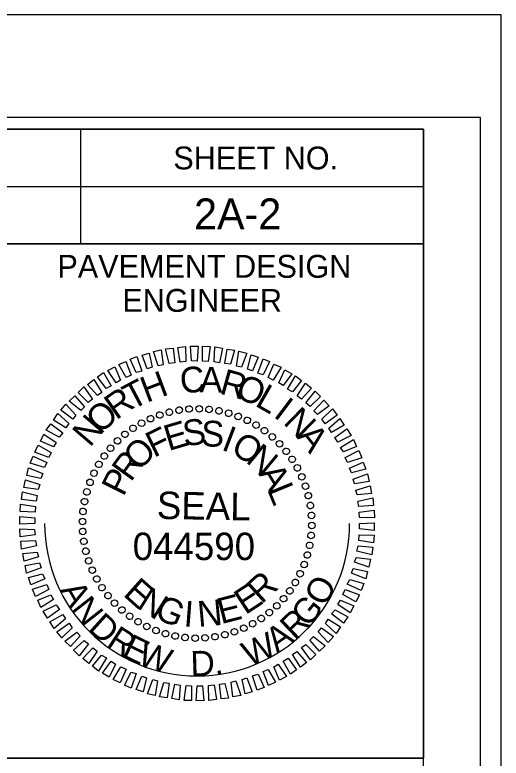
# Model space of a CAD drawing. Extents: x 1497225 to 1499181, y 579958 to 582278.
# Drawn here: x 1498802.9 to 1498909.2, y 580895.5 to 581058 of the extents above; entities that cross this region are included whole.
import ezdxf

# ---------------------------------------------------------------- set-up
doc = ezdxf.new("R2010")
doc.units = 0
for name, color, linetype in [('Scratch_Level_0', 7, 'Continuous'), ('Sheet Cutting Line CELL', 7, 'Continuous'), ('Sheet Data Field CELL', 7, 'Continuous'), ('Sheet Plot Border Inside CELL', 7, 'Continuous'), ('Sheet Plot Border Outside CELL', 7, 'Continuous'), ('Sheet Professional Seal CELL', 7, 'Continuous'), ('Sheet Sticker Exception Certification CELL', 7, 'Continuous'), ('Sheet Typical CELL', 7, 'Continuous')]:
    doc.layers.add(name, color=color, linetype=linetype)

msp = doc.modelspace()

# ---------------------------------------------------------------- linework, layer by layer
at = {"layer": 'Scratch_Level_0'}
msp.add_arc((1498842.73, 580946.79), 33.36, 180, 360, dxfattribs=at)
at = {"layer": 'Sheet Cutting Line CELL'}
msp.add_line((1498909.23, 581058.02), (1497225.23, 581058.02), dxfattribs=at)
at = {"layer": 'Sheet Plot Border Inside CELL'}
msp.add_lwpolyline([(1498904.73, 581035.57), (1497238.23, 581035.57), (1497238.23, 579980.47), (1498904.73, 579980.47)], close=True, dxfattribs=at)
at = {"layer": 'Sheet Plot Border Outside CELL'}
msp.add_lwpolyline([(1498909.23, 581058.02), (1497225.23, 581058.02), (1497225.23, 579958.02), (1498909.23, 579958.02)], close=True, dxfattribs=at)
at = {"layer": 'Sheet Professional Seal CELL'}
for p, q in [((1498838.83, 580971.54), (1498838.83, 580971.54)), ((1498840.98, 580971.84), (1498840.98, 580971.84)), ((1498843.18, 580971.89), (1498843.18, 580971.89)), ((1498845.38, 580971.74), (1498845.38, 580971.74)), ((1498847.53, 580971.39), (1498847.53, 580971.39)), ((1498832.53, 580969.74), (1498832.53, 580969.74)), ((1498834.53, 580970.54), (1498834.53, 580970.54)), ((1498836.63, 580971.14), (1498836.63, 580971.14)), ((1498849.63, 580970.94), (1498849.63, 580970.94)), ((1498851.73, 580970.24), (1498851.73, 580970.24)), ((1498830.58, 580968.74), (1498830.58, 580968.74)), ((1498853.73, 580969.34), (1498853.73, 580969.34)), ((1498855.68, 580968.34), (1498855.68, 580968.34)), ((1498826.93, 580966.34), (1498826.93, 580966.34)), ((1498828.68, 580967.59), (1498828.68, 580967.59)), ((1498857.48, 580967.09), (1498857.48, 580967.09)), ((1498825.28, 580964.84), (1498825.28, 580964.84)), ((1498859.23, 580965.74), (1498859.23, 580965.74)), ((1498823.78, 580963.29), (1498823.78, 580963.29)), ((1498860.78, 580964.24), (1498860.78, 580964.24)), ((1498822.43, 580961.54), (1498822.43, 580961.54)), ((1498862.28, 580962.59), (1498862.28, 580962.59)), ((1498863.53, 580960.84), (1498863.53, 580960.84)), ((1498821.18, 580959.74), (1498821.18, 580959.74)), ((1498864.68, 580958.94), (1498864.68, 580958.94)), ((1498820.18, 580957.79), (1498820.18, 580957.79)), ((1498865.68, 580956.99), (1498865.68, 580956.99)), ((1498819.28, 580955.79), (1498819.28, 580955.79)), ((1498866.48, 580954.99), (1498866.48, 580954.99)), ((1498818.58, 580953.69), (1498818.58, 580953.69)), ((1498867.08, 580952.89), (1498867.08, 580952.89)), ((1498818.13, 580951.59), (1498818.13, 580951.59)), ((1498867.48, 580950.69), (1498867.48, 580950.69)), ((1498817.78, 580949.44), (1498817.78, 580949.44)), ((1498867.78, 580948.54), (1498867.78, 580948.54)), ((1498817.63, 580947.24), (1498817.63, 580947.24)), ((1498842.73, 580946.79), (1498842.73, 580946.79)), ((1498867.83, 580946.34), (1498867.83, 580946.34)), ((1498817.68, 580945.04), (1498817.68, 580945.04)), ((1498867.68, 580944.14), (1498867.68, 580944.14)), ((1498817.98, 580942.89), (1498817.98, 580942.89)), ((1498867.33, 580941.99), (1498867.33, 580941.99)), ((1498818.38, 580940.69), (1498818.38, 580940.69)), ((1498866.88, 580939.89), (1498866.88, 580939.89)), ((1498818.98, 580938.59), (1498818.98, 580938.59)), ((1498866.18, 580937.79), (1498866.18, 580937.79)), ((1498819.78, 580936.59), (1498819.78, 580936.59)), ((1498865.28, 580935.79), (1498865.28, 580935.79)), ((1498820.78, 580934.64), (1498820.78, 580934.64)), ((1498864.28, 580933.84), (1498864.28, 580933.84)), ((1498821.93, 580932.74), (1498821.93, 580932.74)), ((1498823.18, 580930.99), (1498823.18, 580930.99)), ((1498863.03, 580932.04), (1498863.03, 580932.04)), ((1498824.68, 580929.34), (1498824.68, 580929.34)), ((1498861.68, 580930.29), (1498861.68, 580930.29)), ((1498826.23, 580927.84), (1498826.23, 580927.84)), ((1498860.18, 580928.74), (1498860.18, 580928.74)), ((1498827.98, 580926.49), (1498827.98, 580926.49)), ((1498856.78, 580925.99), (1498856.78, 580925.99)), ((1498858.53, 580927.24), (1498858.53, 580927.24)), ((1498829.78, 580925.24), (1498829.78, 580925.24)), ((1498831.73, 580924.24), (1498831.73, 580924.24)), ((1498854.88, 580924.84), (1498854.88, 580924.84)), ((1498833.73, 580923.34), (1498833.73, 580923.34)), ((1498835.83, 580922.64), (1498835.83, 580922.64)), ((1498848.83, 580922.44), (1498848.83, 580922.44)), ((1498850.93, 580923.04), (1498850.93, 580923.04)), ((1498852.93, 580923.84), (1498852.93, 580923.84)), ((1498837.93, 580922.19), (1498837.93, 580922.19)), ((1498840.08, 580921.84), (1498840.08, 580921.84)), ((1498842.28, 580921.69), (1498842.28, 580921.69)), ((1498844.48, 580921.74), (1498844.48, 580921.74)), ((1498846.63, 580922.04), (1498846.63, 580922.04))]:
    msp.add_line(p, q, dxfattribs=at)
for points in [[(1498834.23, 580981.24), (1498833.18, 580984.39), (1498834.88, 580984.74), (1498835.28, 580981.49)], [(1498836.63, 580981.79), (1498835.83, 580984.99), (1498837.48, 580985.14), (1498837.83, 580981.94)], [(1498839.03, 580982.09), (1498838.48, 580985.29), (1498840.18, 580985.49), (1498840.23, 580982.24)], [(1498841.53, 580982.34), (1498841.28, 580985.59), (1498842.93, 580985.54), (1498842.73, 580982.29)], [(1498843.93, 580982.29), (1498843.93, 580985.54), (1498845.58, 580985.49), (1498845.13, 580982.24)], [(1498846.43, 580982.14), (1498846.63, 580985.39), (1498848.28, 580985.09), (1498847.63, 580981.94)], [(1498848.83, 580981.74), (1498849.28, 580984.94), (1498850.93, 580984.69), (1498850.03, 580981.59)], [(1498851.38, 580981.19), (1498851.88, 580984.44), (1498853.58, 580984.04), (1498852.43, 580980.94)], [(1498829.38, 580979.79), (1498828.08, 580982.69), (1498829.58, 580983.29), (1498830.63, 580980.09)], [(1498831.83, 580980.59), (1498830.68, 580983.59), (1498832.23, 580984.04), (1498832.88, 580980.94)], [(1498853.78, 580980.54), (1498854.53, 580983.64), (1498856.08, 580983.14), (1498854.83, 580980.19)], [(1498856.03, 580979.64), (1498857.18, 580982.79), (1498858.58, 580982.19), (1498857.18, 580979.29)], [(1498825.03, 580977.54), (1498823.18, 580980.24), (1498824.73, 580981.04), (1498825.98, 580978.14)], [(1498827.18, 580978.74), (1498825.58, 580981.54), (1498827.13, 580982.24), (1498828.28, 580979.19)], [(1498858.28, 580978.69), (1498859.53, 580981.64), (1498861.08, 580980.94), (1498859.38, 580978.14)], [(1498822.83, 580976.29), (1498820.98, 580978.84), (1498822.28, 580979.79), (1498823.93, 580976.89)], [(1498860.58, 580977.54), (1498861.93, 580980.39), (1498863.43, 580979.54), (1498861.53, 580976.94)], [(1498820.93, 580974.79), (1498818.78, 580977.19), (1498820.13, 580978.24), (1498821.88, 580975.44)], [(1498862.53, 580976.19), (1498864.28, 580979.09), (1498865.58, 580978.04), (1498863.63, 580975.59)], [(1498818.93, 580973.24), (1498816.73, 580975.44), (1498817.93, 580976.64), (1498819.88, 580973.94)], [(1498864.58, 580974.69), (1498866.43, 580977.44), (1498867.73, 580976.34), (1498865.53, 580973.99)], [(1498817.28, 580971.49), (1498814.73, 580973.54), (1498815.98, 580974.69), (1498818.08, 580972.29)], [(1498866.48, 580973.14), (1498868.53, 580975.74), (1498869.73, 580974.54), (1498867.43, 580972.39)], [(1498815.53, 580969.59), (1498812.93, 580971.54), (1498814.03, 580972.84), (1498816.23, 580970.49)], [(1498868.28, 580971.39), (1498870.43, 580973.74), (1498871.63, 580972.54), (1498869.03, 580970.59)], [(1498870.03, 580969.59), (1498872.33, 580971.84), (1498873.38, 580970.49), (1498870.73, 580968.59)], [(1498814.03, 580967.69), (1498811.33, 580969.39), (1498812.28, 580970.84), (1498814.68, 580968.64)], [(1498871.53, 580967.64), (1498873.98, 580969.74), (1498874.93, 580968.29), (1498872.13, 580966.69)], [(1498812.53, 580965.69), (1498809.73, 580967.19), (1498810.73, 580968.59), (1498813.33, 580966.59)], [(1498811.33, 580963.54), (1498808.48, 580964.79), (1498809.23, 580966.34), (1498811.93, 580964.49)], [(1498872.83, 580965.59), (1498875.48, 580967.49), (1498876.43, 580965.99), (1498873.53, 580964.59)], [(1498874.13, 580963.39), (1498876.93, 580965.14), (1498877.58, 580963.59), (1498874.73, 580962.44)], [(1498810.33, 580961.24), (1498807.23, 580962.39), (1498807.98, 580963.94), (1498810.83, 580962.34)], [(1498809.33, 580959.04), (1498806.23, 580959.94), (1498806.88, 580961.49), (1498809.88, 580960.09)], [(1498875.13, 580961.24), (1498878.08, 580962.74), (1498878.73, 580961.14), (1498875.63, 580960.14)], [(1498876.03, 580958.89), (1498879.08, 580960.19), (1498879.63, 580958.64), (1498876.53, 580957.84)], [(1498808.58, 580956.64), (1498805.48, 580957.29), (1498805.83, 580958.94), (1498808.98, 580957.69)], [(1498876.83, 580956.49), (1498880.03, 580957.64), (1498880.33, 580955.99), (1498877.18, 580955.44)], [(1498807.93, 580954.24), (1498804.83, 580954.64), (1498805.18, 580956.34), (1498808.33, 580955.29)], [(1498877.43, 580954.09), (1498880.58, 580955.04), (1498880.88, 580953.34), (1498877.73, 580953.04)], [(1498807.53, 580951.69), (1498804.33, 580951.99), (1498804.53, 580953.69), (1498807.78, 580952.89)], [(1498877.88, 580951.69), (1498881.13, 580952.39), (1498881.28, 580950.69), (1498878.08, 580950.49)], [(1498807.28, 580949.29), (1498804.03, 580949.39), (1498804.13, 580951.04), (1498807.38, 580950.49)], [(1498878.18, 580949.29), (1498881.43, 580949.69), (1498881.53, 580947.99), (1498878.28, 580948.09)], [(1498807.23, 580946.79), (1498803.98, 580946.64), (1498803.98, 580948.34), (1498807.23, 580947.99)], [(1498878.23, 580946.79), (1498881.48, 580946.94), (1498881.48, 580945.24), (1498878.23, 580945.59)], [(1498807.28, 580944.29), (1498804.03, 580943.89), (1498803.93, 580945.59), (1498807.18, 580945.49)], [(1498878.18, 580944.29), (1498881.43, 580944.19), (1498881.33, 580942.54), (1498878.08, 580943.09)], [(1498807.58, 580941.89), (1498804.33, 580941.19), (1498804.18, 580942.89), (1498807.38, 580943.09)], [(1498808.03, 580939.49), (1498804.88, 580938.54), (1498804.58, 580940.24), (1498807.73, 580940.54)], [(1498877.93, 580941.89), (1498881.13, 580941.59), (1498880.93, 580939.89), (1498877.68, 580940.69)], [(1498877.53, 580939.34), (1498880.63, 580938.94), (1498880.28, 580937.24), (1498877.13, 580938.29)], [(1498808.63, 580937.09), (1498805.43, 580935.94), (1498805.13, 580937.59), (1498808.28, 580938.14)], [(1498809.43, 580934.69), (1498806.38, 580933.39), (1498805.83, 580934.94), (1498808.93, 580935.74)], [(1498876.88, 580936.94), (1498879.98, 580936.29), (1498879.63, 580934.64), (1498876.48, 580935.89)], [(1498876.13, 580934.54), (1498879.23, 580933.64), (1498878.58, 580932.09), (1498875.58, 580933.49)], [(1498810.33, 580932.34), (1498807.38, 580930.84), (1498806.73, 580932.44), (1498809.83, 580933.44)], [(1498875.13, 580932.34), (1498878.23, 580931.19), (1498877.48, 580929.64), (1498874.63, 580931.24)], [(1498811.33, 580930.19), (1498808.53, 580928.44), (1498807.88, 580929.99), (1498810.73, 580931.14)], [(1498812.63, 580927.99), (1498809.98, 580926.09), (1498809.03, 580927.59), (1498811.93, 580928.99)], [(1498874.13, 580930.04), (1498876.98, 580928.79), (1498876.23, 580927.24), (1498873.53, 580929.09)], [(1498872.93, 580927.89), (1498875.73, 580926.39), (1498874.73, 580924.99), (1498872.13, 580926.99)], [(1498813.93, 580925.94), (1498811.48, 580923.84), (1498810.53, 580925.29), (1498813.33, 580926.89)], [(1498871.43, 580925.89), (1498874.13, 580924.19), (1498873.18, 580922.74), (1498870.78, 580924.94)], [(1498815.43, 580923.99), (1498813.13, 580921.74), (1498812.08, 580923.09), (1498814.73, 580924.99)], [(1498817.18, 580922.19), (1498815.03, 580919.84), (1498813.83, 580921.04), (1498816.43, 580922.99)], [(1498869.93, 580923.99), (1498872.53, 580922.04), (1498871.43, 580920.74), (1498869.23, 580923.09)], [(1498818.98, 580920.44), (1498816.93, 580917.84), (1498815.73, 580919.04), (1498818.03, 580921.19)], [(1498868.18, 580922.09), (1498870.73, 580920.04), (1498869.48, 580918.89), (1498867.38, 580921.29)], [(1498820.88, 580918.89), (1498819.03, 580916.14), (1498817.73, 580917.24), (1498819.93, 580919.59)], [(1498866.53, 580920.34), (1498868.73, 580918.14), (1498867.53, 580916.94), (1498865.58, 580919.64)], [(1498822.93, 580917.39), (1498821.18, 580914.49), (1498819.88, 580915.54), (1498821.83, 580917.99)], [(1498864.53, 580918.79), (1498866.68, 580916.39), (1498865.33, 580915.34), (1498863.58, 580918.14)], [(1498824.88, 580916.04), (1498823.53, 580913.19), (1498822.03, 580914.04), (1498823.93, 580916.64)], [(1498860.43, 580916.04), (1498862.28, 580913.34), (1498860.73, 580912.54), (1498859.48, 580915.44)], [(1498862.63, 580917.29), (1498864.48, 580914.74), (1498863.18, 580913.79), (1498861.53, 580916.69)], [(1498827.18, 580914.89), (1498825.93, 580911.94), (1498824.38, 580912.64), (1498826.08, 580915.44)], [(1498829.43, 580913.94), (1498828.28, 580910.79), (1498826.88, 580911.39), (1498828.28, 580914.29)], [(1498858.28, 580914.84), (1498859.88, 580912.04), (1498858.33, 580911.34), (1498857.18, 580914.39)], [(1498831.68, 580913.04), (1498830.93, 580909.94), (1498829.38, 580910.44), (1498830.63, 580913.39)], [(1498853.63, 580912.99), (1498854.78, 580909.99), (1498853.23, 580909.54), (1498852.58, 580912.64)], [(1498856.08, 580913.79), (1498857.38, 580910.89), (1498855.88, 580910.29), (1498854.83, 580913.49)], [(1498834.08, 580912.39), (1498833.58, 580909.14), (1498831.88, 580909.54), (1498833.03, 580912.64)], [(1498836.63, 580911.84), (1498836.18, 580908.64), (1498834.53, 580908.89), (1498835.43, 580911.99)], [(1498839.03, 580911.44), (1498838.83, 580908.19), (1498837.18, 580908.49), (1498837.83, 580911.64)], [(1498841.53, 580911.29), (1498841.53, 580908.04), (1498839.88, 580908.09), (1498840.33, 580911.34)], [(1498843.93, 580911.24), (1498844.18, 580907.99), (1498842.53, 580908.04), (1498842.73, 580911.29)], [(1498846.43, 580911.49), (1498846.98, 580908.29), (1498845.28, 580908.09), (1498845.23, 580911.34)], [(1498848.83, 580911.79), (1498849.63, 580908.59), (1498847.98, 580908.44), (1498847.63, 580911.64)], [(1498851.23, 580912.34), (1498852.28, 580909.19), (1498850.58, 580908.84), (1498850.18, 580912.09)]]:
    msp.add_lwpolyline(points, close=True, dxfattribs=at)
for centre, major_axis in [((1498834.56, 580970.5), (-0.234, 0.681)), ((1498836.66, 580971.12), (-0.174, 0.699)), ((1498838.8, 580971.56), (-0.113, 0.711)), ((1498840.98, 580971.81), (-0.05, 0.718)), ((1498843.16, 580971.87), (0.013, 0.72)), ((1498845.35, 580971.73), (0.075, 0.716)), ((1498847.51, 580971.41), (0.137, 0.707)), ((1498849.64, 580970.9), (0.198, 0.692)), ((1498830.57, 580968.72), (-0.349, 0.63)), ((1498832.52, 580969.7), (-0.293, 0.658)), ((1498851.71, 580970.2), (0.258, 0.672)), ((1498853.72, 580969.33), (0.316, 0.647)), ((1498828.7, 580967.58), (-0.403, 0.597)), ((1498855.64, 580968.29), (0.371, 0.617)), ((1498826.94, 580966.28), (-0.453, 0.56)), ((1498857.47, 580967.08), (0.423, 0.582)), ((1498859.18, 580965.72), (0.472, 0.543)), ((1498825.3, 580964.83), (-0.5, 0.518)), ((1498860.77, 580964.21), (0.518, 0.5)), ((1498823.8, 580963.24), (-0.543, 0.472)), ((1498862.22, 580962.57), (0.56, 0.453)), ((1498822.44, 580961.53), (-0.582, 0.423)), ((1498863.52, 580960.81), (0.597, 0.403)), ((1498821.23, 580959.71), (-0.617, 0.371)), ((1498820.18, 580957.78), (-0.647, 0.316)), ((1498864.66, 580958.95), (0.63, 0.349)), ((1498819.31, 580955.78), (-0.672, 0.258)), ((1498865.64, 580956.99), (0.658, 0.293)), ((1498866.44, 580954.95), (0.681, 0.234)), ((1498818.62, 580953.7), (-0.692, 0.198)), ((1498867.06, 580952.86), (0.699, 0.174)), ((1498818.11, 580951.57), (-0.707, 0.137)), ((1498817.78, 580949.41), (-0.716, 0.075)), ((1498867.5, 580950.71), (0.711, 0.113)), ((1498867.74, 580948.54), (0.718, 0.05)), ((1498817.65, 580947.23), (-0.72, 0.013)), ((1498867.8, 580946.35), (0.72, -0.013)), ((1498817.71, 580945.04), (-0.718, -0.05)), ((1498817.95, 580942.87), (-0.711, -0.113)), ((1498867.67, 580944.17), (0.716, -0.075)), ((1498867.34, 580942), (0.707, -0.137)), ((1498818.39, 580940.72), (-0.699, -0.174)), ((1498866.83, 580939.88), (0.692, -0.198)), ((1498819.01, 580938.62), (-0.681, -0.234)), ((1498819.81, 580936.59), (-0.658, -0.293)), ((1498866.14, 580937.8), (0.672, -0.258)), ((1498820.79, 580934.63), (-0.63, -0.349)), ((1498865.27, 580935.79), (0.647, -0.316)), ((1498864.22, 580933.87), (0.617, -0.371)), ((1498821.93, 580932.76), (-0.597, -0.403)), ((1498863.02, 580932.05), (0.582, -0.423)), ((1498823.23, 580931.01), (-0.56, -0.453)), ((1498861.65, 580930.34), (0.543, -0.472)), ((1498824.68, 580929.37), (-0.518, -0.5)), ((1498860.15, 580928.75), (0.5, -0.518)), ((1498826.27, 580927.86), (-0.472, -0.543)), ((1498827.98, 580926.5), (-0.423, -0.582)), ((1498858.51, 580927.3), (0.453, -0.56)), ((1498829.81, 580925.29), (-0.371, -0.617)), ((1498854.88, 580924.85), (0.349, -0.63)), ((1498856.75, 580926), (0.403, -0.597)), ((1498831.73, 580924.25), (-0.316, -0.647)), ((1498833.74, 580923.37), (-0.258, -0.672)), ((1498852.93, 580923.88), (0.293, -0.658)), ((1498835.81, 580922.68), (-0.198, -0.692)), ((1498837.94, 580922.17), (-0.137, -0.707)), ((1498840.1, 580921.85), (-0.075, -0.716)), ((1498842.29, 580921.71), (-0.013, -0.72)), ((1498844.48, 580921.77), (0.05, -0.718)), ((1498846.65, 580922.02), (0.113, -0.711)), ((1498848.79, 580922.45), (0.174, -0.699)), ((1498850.89, 580923.08), (0.234, -0.681))]:
    msp.add_ellipse(centre, major_axis=major_axis, ratio=0.999708, dxfattribs=at)
at = {"layer": 'Sheet Sticker Exception Certification CELL'}
msp.add_line((1498692.18, 580895.47), (1498892.22, 580895.47), dxfattribs=at)
at = {"layer": 'Sheet Typical CELL'}
for p, q in [((1498817.23, 581032.97), (1498817.23, 581007.97)), ((1498692.18, 581020.47), (1498892.23, 581020.47))]:
    msp.add_line(p, q, dxfattribs=at)
for points in [[(1498892.23, 581033.02), (1497392.23, 581033.02), (1497392.23, 579983.02), (1498892.23, 579983.02)], [(1498692.18, 581033.02), (1498892.23, 581033.02), (1498892.23, 581007.97), (1498692.18, 581007.97)], [(1498792.23, 581007.97), (1498892.23, 581007.97), (1498892.23, 580895.47), (1498792.23, 580895.47)]]:
    msp.add_lwpolyline(points, close=True, dxfattribs=at)

# ---------------------------------------------------------------- texts
at = {"layer": 'Sheet Data Field CELL'}
msp.add_text('2A-2', height=6.75, dxfattribs=at).set_placement((1498842.07, 581011.12))
at = {"layer": 'Sheet Professional Seal CELL'}
for s, height, rotation, p in [('C', 5.64, 6.2199, (1498839.28, 580975.14)), ('A', 5.64, 359.0203, (1498843.23, 580975.44)), ('H', 5.64, 20.6195, (1498831.68, 580973.14)), ('R', 5.64, 344.6211, (1498847.43, 580975.24)), ('T', 5.64, 27.8198, (1498828.43, 580971.49)), ('O', 5.64, 337.4212, (1498850.78, 580974.49)), ('R', 5.64, 35.0205, (1498825.03, 580969.29)), ('L', 5.64, 330.2209, (1498855.18, 580972.64)), ('O', 5.64, 42.2217, (1498821.58, 580966.19)), ('I', 5.64, 323.0201, (1498859.23, 580970.24)), ('N', 5.64, 315.8189, (1498861.38, 580968.69)), ('N', 5.64, 49.4235, (1498819.28, 580963.29)), ('S', 5.64, 7.2556, (1498839.93, 580963.64)), ('F', 5.64, 25.967, (1498833.28, 580961.09)), ('E', 5.64, 16.6111, (1498836.48, 580962.59)), ('S', 5.64, 357.9004, (1498843.53, 580963.69)), ('I', 5.64, 339.1896, (1498847.83, 580962.99)), ('O', 5.64, 329.8335, (1498849.83, 580962.29)), ('A', 5.64, 308.6172, (1498864.33, 580965.74)), ('O', 5.64, 44.6812, (1498829.98, 580958.14)), ('N', 5.64, 320.4766, (1498853.18, 580960.29)), ('R', 5.64, 54.0397, (1498828.23, 580955.69)), ('P', 5.64, 63.3989, (1498826.63, 580952.49)), ('A', 5.64, 301.7603, (1498856.03, 580957.69)), ('L', 5.64, 292.4008, (1498857.98, 580954.24)), ('SEAL', 5.998, 359, (1498833.88, 580947.79)), ('R', 5.64, 42.4814, (1498856.83, 580929.04)), ('E', 5.64, 318.2769, (1498826.33, 580931.14)), ('E', 5.64, 33.1241, (1498853.28, 580926.69)), ('O', 5.5, 60.7091, (1498870.66, 580928.39)), ('A', 5.5, 299.9114, (1498812.62, 580932.22)), ('N', 5.64, 327.634, (1498829.33, 580928.44)), ('N', 5.5, 308.0972, (1498815, 580928.08)), ('G', 5.64, 336.9902, (1498833.13, 580926.19)), ('E', 5.64, 14.4118, (1498847.98, 580924.74)), ('G', 5.5, 50.7774, (1498867.07, 580923.85)), ('I', 5.64, 355.7012, (1498839.68, 580924.29)), ('N', 5.64, 5.0564, (1498843.03, 580924.14)), ('R', 5.5, 43.851, (1498864.12, 580921.08)), ('D', 5.5, 318.0289, (1498818.64, 580923.58)), ('R', 5.5, 327.1735, (1498822.64, 580920.04)), ('A', 5.5, 35.6652, (1498860.24, 580918.29)), ('E', 5.5, 334.1, (1498826.01, 580917.82)), ('W', 5.5, 24.0591, (1498854.15, 580915.35)), ('W', 5.5, 340.6829, (1498829.44, 580916.09)), ('D', 5.5, 1.7342, (1498841.35, 580913.37)), ('.', 5.5, 10.8788, (1498846.68, 580913.57))]:
    msp.add_text(s, height=height, rotation=rotation, dxfattribs=at).set_placement(p)
msp.add_text('044590', height=5.998, dxfattribs=at).set_placement((1498828.64, 580938.78))
at = {"layer": 'Sheet Typical CELL'}
for s, height, p in [('SHEET NO.', 5, (1498837.53, 581024.22)), ('PAVEMENT DESIGN', 5.0001, (1498812.18, 581000.52)), ('ENGINEER', 5, (1498826.38, 580993.07))]:
    msp.add_text(s, height=height, dxfattribs=at).set_placement(p)

doc.saveas('drawing.dxf')
